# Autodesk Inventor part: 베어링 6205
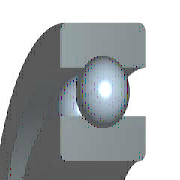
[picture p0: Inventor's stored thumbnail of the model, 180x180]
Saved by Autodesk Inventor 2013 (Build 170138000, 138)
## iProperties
IsCustomPart: 1
Company: 한국ATC센터
Created: 2014-10
Part Number: 베어링 6205
Material: 강, 연강
Description: 깊은 그루브 볼 베어링
Document SubType Name: Modeling
Standard: KS B 2023
Designer: 한국ATC센터
Standards Organization: KS
Language: ko-KR
Size Designation: 6205 - 25 x 52 x 15
Categories: <MemberInstance><Categories><Category DisplayName="샤프트 부품" InternalName="7f7aeb1f-a693-4053-b835-cee3144e0d98" Mnemonic="SHFT"><Category DisplayName="베어링" Inter
Density: 7.86 g/cm^3
Mass: 129.543 g
Surface Area: 107.326 cm^2
Volume: 16.4813 cm^3
Author: KYOUNG IL JANG
Revision Number: 1
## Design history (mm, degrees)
sketch "스케치" dims "d0" = 7.02 (= -0.26 x WD + 0.26 x BD)
  geometry: L1 (3.99, 19.25)-(11.01, 19.25); L2 (7.5, 19.25)-(7.5, 15.74); L3 (7.5, 19.25)-(7.5, 22.76); L4 (4.892, 16.901)-(0, 16.901); L5 (0, 12.5)-(15, 12.5); L6 (4.892, 21.599)-(0, 21.599); L7 (0, 26)-(15, 26); L8 (15, 12.5)-(15, 16.901); L9 (10.108, 16.901)-(15, 16.901); L10 (10.108, 21.599)-(15, 21.599); L11 (15, 26)-(15, 21.599); L12 (-1.4, 0)-(8.4, 0) reference; L13 (0, -0.3)-(0, 5.3) reference
  constraints: 22 end point, 4 point on line, 2 collinear, 2 perpendicular, 2 symmetric about line, 1 midpoint, 1 parallel, 14 other
  dimensions: "d9" = 25 diameter of L5 L12 (= WD); "d11" = 52 diameter of L7 L12 (= BD); "d12" = 15 distance between parallel lines of L8 L13 (= KB); "d13" = 33.802 diameter of L9 L12 (= 0.326 x BD + 0.674 x WD)
revolve "본체" stored, may be unused: angle "d6" = 90 deg
revolve "볼" stored, may be unused: angle "d7" = 90 deg
pattern_circular "IDS_ARRAYBALL[SIMPL:T]" dims angle "d3" = 360 deg
body "Solid1"
fillet "모깎기1" dims "d1" = 1 (= KRS)
other parameters: "WD" = 25 [user parameter; used in 5 equation terms], "BD" = 52 [user parameter; used in 5 equation terms], "KB" = 15 [user parameter; used in 1 equation term], "KRS" = 1 [user parameter; used in 1 equation term], "d4" = 0, "d5" = 0, "d8" = 0, "d14" = 0, "d15" = 0, "BBA" = 0 [user parameter], "BC0" = 7800000 [user parameter], "BC" = 1.4e+07 [user parameter], "BR" = 26 (= 0.5 x BD) [user parameter], "WR" = 12.5 (= 0.5 x WD) [user parameter]
